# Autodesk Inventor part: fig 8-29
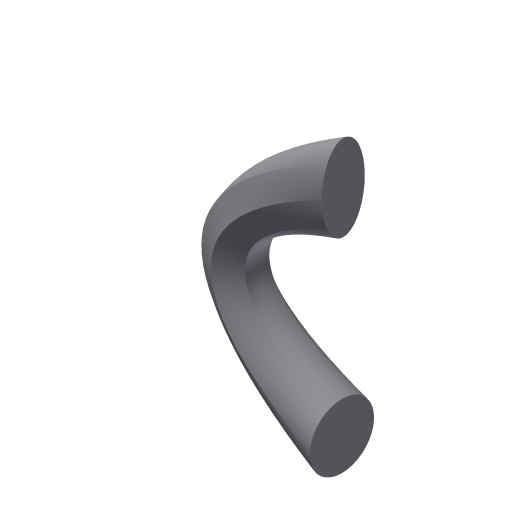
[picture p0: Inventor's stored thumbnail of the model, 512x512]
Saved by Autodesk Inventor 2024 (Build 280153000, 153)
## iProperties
Created: 2008-06
Part Number: fig 8-29
Document SubType Name: Modeling
Designer: CADCIM
Density: 1 g/cm^3
Material: Generic
Appearance: Default
Author: CADCIM
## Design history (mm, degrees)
sketch "Sketch1"
  geometry: L1 (-0.077, 5.773)-(4.961, 2.953); L2 (4.961, 2.953)-(5.038, -2.82); L3 (5.038, -2.82)-(0.077, -5.773); L4 (0.077, -5.773)-(-4.961, -2.953); L5 (-4.961, -2.953)-(-5.038, 2.82); L6 (-5.038, 2.82)-(-0.077, 5.773); 1 further point
  constraints: 12 end point, 13 other
  dimensions: "d0" = 10 distance between parallel lines of L2 L5
workplane "Work Plane1"
sketch "Sketch2"
  geometry: C1 r 7.5 at (-0.159, -25); 1 further point
  constraints: 1 centre point
  dimensions: "d2" = 15 diameter of C1; "d3" = 25 vertical distance of C1.centre point (0, 0)
sketch "Sketch3" dims "d4" = 10, "d5" = 5
  geometry: 2 further points; 1 other entity
  constraints: 2 other
  dimensions: "d6" = 25 vertical distance of point (0.175, 25) point (0, 0)
loft "Loft1" sketch "Sketch2", "Sketch3" dims "d7" = 0, "d8" = 90 deg, "d9" = 0, "d10" = 90 deg, "d11" = 0, "d12" = 90 deg
body "Solid1"
other parameters: "d1" = 25
